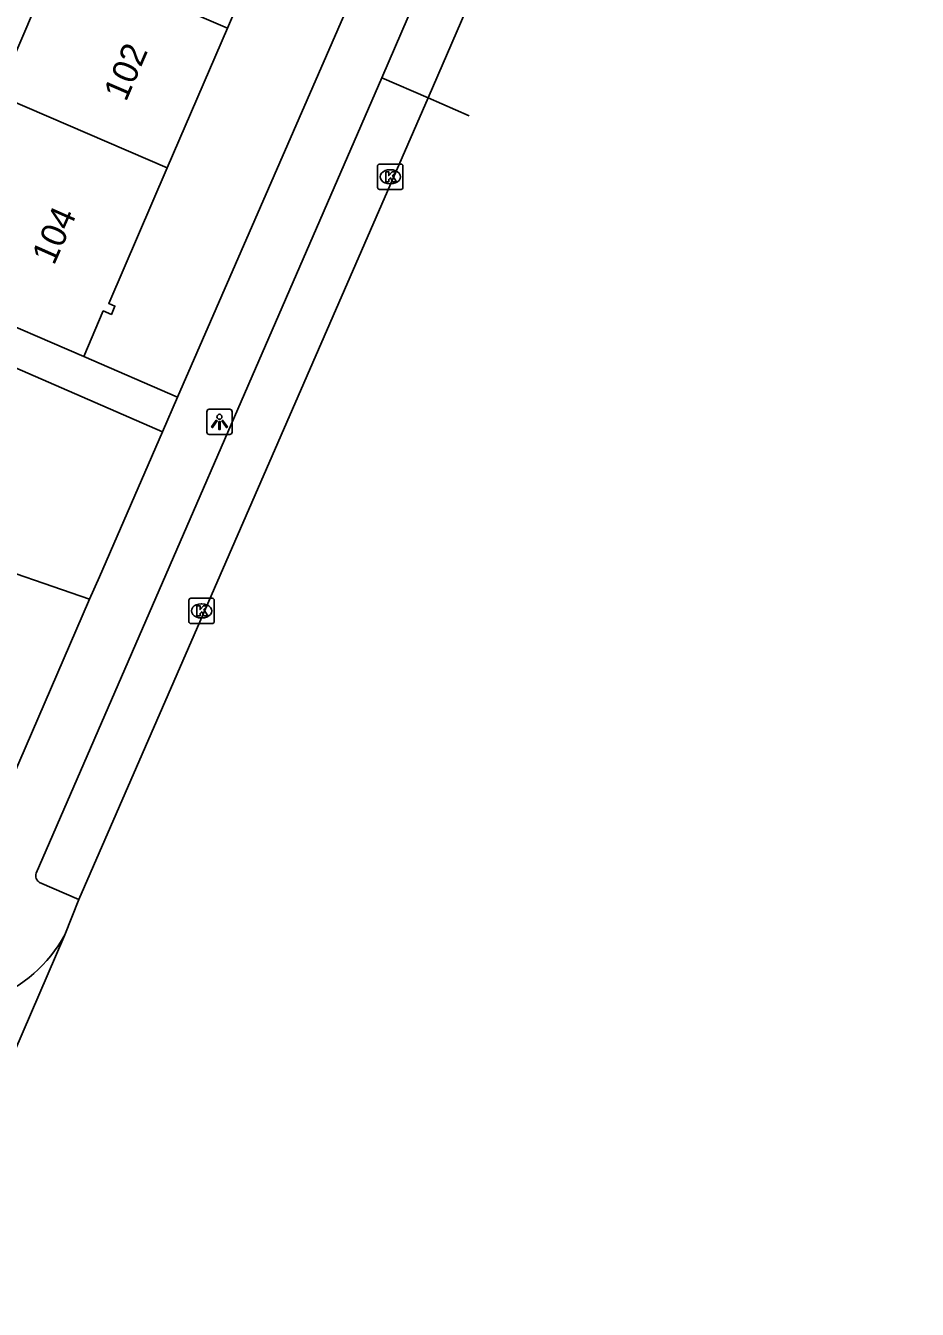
# Model space of a CAD drawing. Extents: x 162812 to 163818, y 381639 to 382470.
# Drawn here: x 163647.2 to 163682.4, y 381768.6 to 381819.3 of the extents above; entities that cross this region are included whole.
import ezdxf

# ---------------------------------------------------------------- set-up
doc = ezdxf.new("R2010")
doc.units = 0
for name, color, linetype in [('IMGEO_Kolk', 7, 'Continuous'), ('IMGEO_Lichtpunt', 7, 'Continuous'), ('IMGEO_Pand', 7, 'Continuous'), ('IMGEO_Pand_nummerreeks', 7, 'Continuous'), ('IMGEO_Parkeervlak_open', 7, 'Continuous'), ('IMGEO_Rijbaan_lokaal_open', 7, 'Continuous'), ('IMGEO_Voetpad_open', 7, 'Continuous')]:
    doc.layers.add(name, color=color, linetype=linetype)

msp = doc.modelspace()

# ---------------------------------------------------------------- linework, layer by layer
at = {"layer": 'IMGEO_Kolk'}
for p, q in [((163661.07, 381812.931), (163661.07, 381813.783)), ((163661.145, 381813.857), (163661.997, 381813.857)), ((163662.071, 381813.783), (163662.071, 381812.931)), ((163661.558, 381813.637), (163661.583, 381813.637)), ((163661.997, 381812.857), (163661.145, 381812.857)), ((163661.581, 381813.077), (163661.556, 381813.077)), ((163653.61, 381795.778), (163653.61, 381796.63)), ((163653.685, 381796.704), (163654.537, 381796.704)), ((163654.611, 381796.63), (163654.611, 381795.778)), ((163654.098, 381796.484), (163654.123, 381796.484)), ((163654.537, 381795.704), (163653.685, 381795.704)), ((163654.121, 381795.924), (163654.096, 381795.924))]:
    msp.add_line(p, q, dxfattribs=at)
for points in [[(163661.07, 381812.931), (163661.07, 381813.783)], [(163661.145, 381813.857), (163661.997, 381813.857)], [(163662.071, 381813.783), (163662.071, 381812.931)], [(163661.391, 381813.557), (163661.514, 381813.557), (163661.514, 381813.406), (163661.644, 381813.557), (163661.808, 381813.557), (163661.662, 381813.406), (163661.815, 381813.157), (163661.663, 381813.157), (163661.578, 381813.321), (163661.514, 381813.254), (163661.514, 381813.157), (163661.391, 381813.157), (163661.391, 381813.557)], [(163661.997, 381812.857), (163661.145, 381812.857)], [(163653.61, 381795.778), (163653.61, 381796.63)], [(163653.685, 381796.704), (163654.537, 381796.704)], [(163654.611, 381796.63), (163654.611, 381795.778)], [(163653.931, 381796.404), (163654.054, 381796.404), (163654.054, 381796.253), (163654.184, 381796.404), (163654.348, 381796.404), (163654.202, 381796.253), (163654.355, 381796.004), (163654.203, 381796.004), (163654.118, 381796.168), (163654.054, 381796.101), (163654.054, 381796.004), (163653.931, 381796.004), (163653.931, 381796.404)], [(163654.537, 381795.704), (163653.685, 381795.704)]]:
    msp.add_lwpolyline(points, dxfattribs=at)
for centre, start, end in [((163661.147, 381813.781), 91.552, 178.448), ((163661.147, 381813.781), 91.552, 178.448), ((163661.995, 381813.781), 1.552, 88.448), ((163661.995, 381813.781), 1.552, 88.448), ((163661.147, 381812.933), 181.552, 268.448), ((163661.147, 381812.933), 181.552, 268.448), ((163661.995, 381812.933), 271.552, 358.448), ((163661.995, 381812.933), 271.552, 358.448), ((163653.687, 381796.628), 91.552, 178.448), ((163653.687, 381796.628), 91.552, 178.448), ((163654.535, 381796.628), 1.552, 88.448), ((163654.535, 381796.628), 1.552, 88.448), ((163653.687, 381795.78), 181.552, 268.448), ((163653.687, 381795.78), 181.552, 268.448), ((163654.535, 381795.78), 271.552, 358.448), ((163654.535, 381795.78), 271.552, 358.448)]:
    msp.add_arc(centre, 0.0765, start, end, dxfattribs=at)
for centre, major_axis, ratio, start_param, end_param in [((163661.557, 381813.357), (-0.387, 0.002), 0.722429, 4.712389, 7.853982), ((163661.582, 381813.357), (-0.39, 0.002), 0.717154, 1.570796, 4.712389), ((163654.097, 381796.204), (-0.387, 0.002), 0.722429, 4.712389, 7.853982), ((163654.122, 381796.204), (-0.39, 0.002), 0.717154, 1.570796, 4.712389)]:
    msp.add_ellipse(centre, major_axis=major_axis, ratio=ratio, start_param=start_param, end_param=end_param, dxfattribs=at)
at = {"layer": 'IMGEO_Lichtpunt'}
for p, q in [((163655.223, 381804.17), (163654.415, 381804.17)), ((163655.223, 381804.17), (163654.415, 381804.17)), ((163654.321, 381804.075), (163654.321, 381803.268)), ((163654.321, 381804.075), (163654.321, 381803.268)), ((163655.317, 381803.268), (163655.317, 381804.075)), ((163655.317, 381803.268), (163655.317, 381804.075)), ((163654.415, 381803.174), (163655.223, 381803.174)), ((163654.415, 381803.174), (163655.223, 381803.174))]:
    msp.add_line(p, q, dxfattribs=at)
for points in [[(163654.695, 381803.739), (163654.734, 381803.711), (163654.546, 381803.449), (163654.508, 381803.476), (163654.695, 381803.739)], [(163654.797, 381803.691), (163654.844, 381803.691), (163654.844, 381803.369), (163654.797, 381803.369), (163654.797, 381803.691)], [(163654.907, 381803.711), (163654.945, 381803.738), (163655.132, 381803.476), (163655.093, 381803.448), (163654.907, 381803.711)]]:
    msp.add_lwpolyline(points, dxfattribs=at)
msp.add_circle((163654.82, 381803.873), 0.0994, dxfattribs=at)
for centre, start, end in [((163654.415, 381804.075), 90, 180), ((163654.415, 381804.075), 90, 180), ((163655.223, 381804.075), 0, 90), ((163655.223, 381804.075), 0, 90), ((163654.415, 381803.268), 180, 270), ((163654.415, 381803.268), 180, 270), ((163655.223, 381803.268), 270, 0), ((163655.223, 381803.268), 270, 360)]:
    msp.add_arc(centre, 0.0946, start, end, dxfattribs=at)
at = {"layer": 'IMGEO_Pand'}
for points in [[(163655.133, 381819.228), (163657.512, 381824.747)], [(163643.748, 381817.6), (163643.789, 381817.696), (163646.087, 381816.705), (163648.422, 381822.122)], [(163648.422, 381822.122), (163648.834, 381821.943), (163655.133, 381819.228)], [(163652.755, 381813.711), (163655.133, 381819.228)], [(163643.748, 381817.6), (163646.456, 381816.425), (163652.755, 381813.711)], [(163649.452, 381806.257), (163650.227, 381808.055), (163650.548, 381807.917), (163650.69, 381808.245), (163650.445, 381808.351), (163652.755, 381813.711)], [(163649.452, 381806.257), (163645.109, 381808.13), (163640.518, 381810.11)], [(163649.682, 381796.662), (163644.937, 381798.301), (163638.287, 381800.598), (163637.961, 381799.666)], [(163649.682, 381796.662), (163646.634, 381789.616)]]:
    msp.add_lwpolyline(points, dxfattribs=at)
at = {"layer": 'IMGEO_Parkeervlak_open'}
msp.add_lwpolyline([(163661.244, 381817.261), (163663.066, 381816.473)], dxfattribs=at)
at = {"layer": 'IMGEO_Rijbaan_lokaal_open'}
for points in [[(163670.768, 381834.258), (163663.066, 381816.473)], [(163663.066, 381816.473), (163649.262, 381784.797)], [(163663.066, 381816.473), (163664.687, 381815.77)], [(163649.262, 381784.797), (163648.708, 381783.399)], [(163648.708, 381783.399), (163642.318, 381768.607)]]:
    msp.add_lwpolyline(points, dxfattribs=at)
msp.add_arc((163643.616, 381786.262), 5.842, 254.4607, 330.6506, dxfattribs=at)
at = {"layer": 'IMGEO_Voetpad_open'}
for points in [[(163682.405, 381873), (163682.334, 381872.821), (163677.466, 381860.963), (163667.683, 381837.944), (163653.164, 381804.647)], [(163661.244, 381817.261), (163668.904, 381835.03)], [(163647.577, 381785.841), (163661.244, 381817.261)], [(163653.164, 381804.647), (163649.452, 381806.257)], [(163646.731, 381805.819), (163652.568, 381803.281)], [(163652.568, 381803.281), (163653.164, 381804.647)], [(163652.568, 381803.281), (163650.071, 381797.555), (163649.682, 381796.662)], [(163649.262, 381784.797), (163647.71, 381785.476)]]:
    msp.add_lwpolyline(points, dxfattribs=at)
msp.add_arc((163647.842, 381785.731), 0.287, 157.4627, 242.5792, dxfattribs=at)

# ---------------------------------------------------------------- texts
at = {"layer": 'IMGEO_Pand_nummerreeks'}
for s, rotation, p in [('102', 66.6836, (163651.123, 381816.29)), ('104', 66.0997, (163648.278, 381809.828))]:
    msp.add_text(s, height=1, rotation=rotation, dxfattribs=at).set_placement(p)

doc.saveas('drawing.dxf')
